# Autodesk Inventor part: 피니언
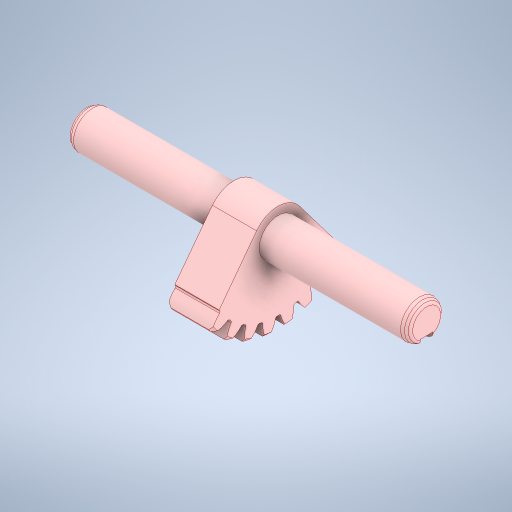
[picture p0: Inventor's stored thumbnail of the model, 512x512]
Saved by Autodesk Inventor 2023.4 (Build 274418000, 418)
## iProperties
Created: 2024-05
Part Number: 피니언
Material: 강철, 탄소
Document SubType Name: Modeling
Designer: EDU-001
Density: 7.85 g/cm^3
Appearance: 기본값
Sending System: Autodesk Inventor 2025
Preprocessor: ST-DEVELOPER v20
Author: jhkim
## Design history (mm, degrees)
node "피니언1"
node "솔리드2"
node "솔리드1"
